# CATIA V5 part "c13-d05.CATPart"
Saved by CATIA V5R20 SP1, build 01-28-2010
Part number: Part1
Bounding box of the stored display mesh (mm): x -62.5 to 62.5, y -75 to 75, z 0 to 20
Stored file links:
  D:\v5_r20\psrt_files_downloaded\c13-catia-v5r20-prt\c13-catia-v5r20-figr-13-22\c13-d05.CATPart
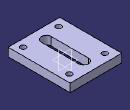
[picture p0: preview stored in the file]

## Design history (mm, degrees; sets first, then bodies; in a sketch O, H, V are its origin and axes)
Body1 (main body)
  Sketch1 on xy-plane, origin (0, 0, 0), H (1, 0, 0), V (0, 1, 0)
    line L1 (62.5, 75) -> (62.5, -75)
    line L2 (62.5, -75) -> (-62.5, -75)
    line L3 (-62.5, -75) -> (-62.5, 75)
    line L4 (-62.5, 75) -> (62.5, 75)
    length L1 = 150
    length L2 = 125
    vertical: L1 V, L3 V
    horizontal: L2 H, L4 H
    equidistance: L1 L3 O, L2 L4 O
  Pad1: profile Sketch1, direction (0, 0, 1), length 20
  Sketch2 on face of Pad1, origin (0, 0, 20), H (1, 0, 0), V (0, 1, 0)
    construction line L1 (0, 45) -> (0, -45)
    point P1 (0, 45)
    line L2 (12, 45) -> (12, -45)
    line L3 (-12, -45) -> (-12, 45)
    arc A1 centre (0, -45) radius 12 from (12, -45) to (-12, -45) cw
    arc A2 centre (0, 45) radius 12 from (-12, 45) to (12, 45) cw
    length L1 = 90
    radius A2 = 12
    coincidence: P1 V
    vertical: L1 V
    tangency: A1 L2, A2 L2, A1 L3, A2 L3
    parallelism: L1 L2
    midpoint: O L1
  Pocket1: profile Sketch2, direction (0, 0, -1), through (limit type 3)
  Sketch3 on face of Pad1, origin (38.7626, -18.4621, 20), H (1, 0, 0), V (0, 1, 0)
    point P1 (5.7374, -38.5379)
    reference projected line E1 (-101.2626, -56.5379) -> (23.7374, -56.5379) from edge [face of Pad1 | face of Pad1]
    reference projected line E2 (23.7374, -56.5379) -> (23.7374, 93.4621) from edge [face of Pad1 | face of Pad1]
    distance P1 E1 = 18
    distance P1 E2 = 18
  Hole1: placed by Sketch3, at (44.5, -57, 20) direction (0, 0, -1), diameter 13, through (limit type 3)
  RectPattern1: of Hole1, direction 1 instances 2, spacing 86, along edge [face of Pad1 | face of Pad1] reversed, direction 2 instances 2, spacing 112, along edge [face of Pad1 | face of Pad1]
